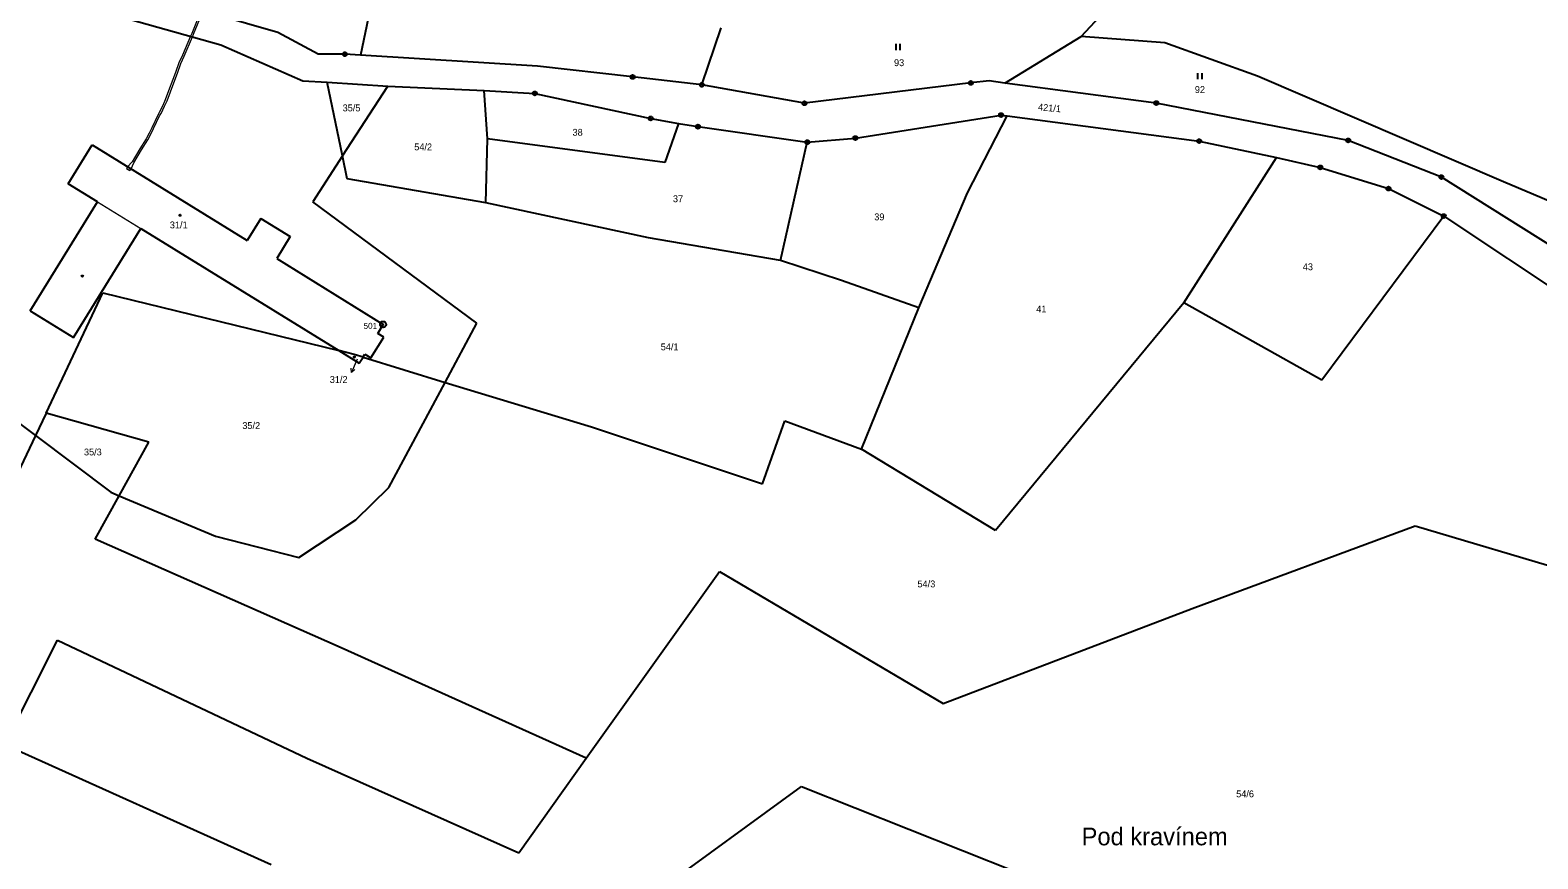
# Model space of a CAD drawing. Extents: x -791548 to -789311, y -1142631 to -1140855.
# Drawn here: x -790140.3 to -789765.7, y -1142374.6 to -1142168.7 of the extents above; entities that cross this region are included whole.
import ezdxf
from ezdxf.enums import TextEntityAlignment as Align

# ---------------------------------------------------------------- set-up
doc = ezdxf.new("R2010")
doc.units = 0
doc.header["$LTSCALE"] = 0.68
for name, color, linetype, lineweight in [('1', 7, 'Continuous', 25), ('13', 7, 'Continuous', 13), ('3', 7, 'Continuous', 25), ('4', 7, 'Continuous', 13), ('5', 7, 'Continuous', 25), ('7', 7, 'Continuous', 13), ('8', 7, 'Continuous', 25)]:
    doc.layers.add(name, color=color, linetype=linetype, lineweight=lineweight)
doc.layers.add('2', color=7, linetype='Continuous')

msp = doc.modelspace()

# ---------------------------------------------------------------- linework, layer by layer
at = {"layer": '1'}
for p, q in [((-790049.96, -1142135.49), (-790058.25, -1142174.9)), ((-790078.79, -1142169.26), (-790128.15, -1142154.89)), ((-789879.15, -1142170.27), (-789866.64, -1142156.74)), ((-790126.91, -1142162.79), (-790092.94, -1142172.32)), ((-790068.73, -1142174.67), (-790078.79, -1142169.26)), ((-789973.41, -1142182.27), (-789968.63, -1142168.11)), ((-789898.1, -1142181.88), (-789879.15, -1142170.27)), ((-789858.35, -1142171.87), (-789879.15, -1142170.27)), ((-790092.94, -1142172.32), (-790072.55, -1142181.25)), ((-789835.32, -1142180.11), (-789858.35, -1142171.87)), ((-790062.15, -1142174.65), (-790068.73, -1142174.67)), ((-790058.25, -1142174.9), (-790062.15, -1142174.65)), ((-790014.24, -1142177.64), (-790058.25, -1142174.9)), ((-789990.63, -1142180.31), (-790014.24, -1142177.64)), ((-790072.55, -1142181.25), (-790066.55, -1142181.6)), ((-790062.72, -1142199.92), (-790066.55, -1142181.6)), ((-790066.55, -1142181.6), (-790051.46, -1142182.57)), ((-789973.41, -1142182.27), (-789990.63, -1142180.31)), ((-789902.03, -1142181.26), (-789906.58, -1142181.8)), ((-789898.1, -1142181.88), (-789902.03, -1142181.26)), ((-789774.23, -1142206.36), (-789835.32, -1142180.11)), ((-790062.72, -1142199.92), (-790051.46, -1142182.57)), ((-790051.46, -1142182.57), (-790027.52, -1142183.69)), ((-790026.68, -1142195.7), (-790027.52, -1142183.69)), ((-790027.52, -1142183.69), (-790014.93, -1142184.4)), ((-790014.93, -1142184.4), (-789986.12, -1142190.62)), ((-789947.92, -1142186.86), (-789973.41, -1142182.27)), ((-789906.58, -1142181.8), (-789947.92, -1142186.86)), ((-789860.49, -1142186.79), (-789898.1, -1142181.88)), ((-789812.79, -1142196.06), (-789860.49, -1142186.79)), ((-789986.12, -1142190.62), (-789979.19, -1142191.84)), ((-789979.19, -1142191.84), (-789982.61, -1142201.56)), ((-789979.19, -1142191.84), (-789974.39, -1142192.66)), ((-789974.39, -1142192.66), (-789947.22, -1142196.51)), ((-789935.26, -1142195.48), (-789899.06, -1142189.78)), ((-789907.39, -1142209.13), (-789897.53, -1142189.94)), ((-789899.06, -1142189.78), (-789897.53, -1142189.94)), ((-789897.53, -1142189.94), (-789849.83, -1142196.25)), ((-790027.09, -1142211.59), (-790026.68, -1142195.7)), ((-789982.61, -1142201.56), (-790026.68, -1142195.7)), ((-789953.84, -1142225.89), (-789947.22, -1142196.51)), ((-789947.22, -1142196.51), (-789935.26, -1142195.48)), ((-789849.83, -1142196.25), (-789830.6, -1142200.28)), ((-789789.62, -1142205.2), (-789812.79, -1142196.06)), ((-790130.87, -1142206.84), (-790124.92, -1142197.19)), ((-790124.92, -1142197.19), (-790086.4, -1142220.91)), ((-790062.72, -1142199.92), (-790070.06, -1142211.32)), ((-790061.52, -1142205.63), (-790062.72, -1142199.92)), ((-789853.67, -1142236.46), (-789830.6, -1142200.28)), ((-789830.6, -1142200.28), (-789819.72, -1142202.78)), ((-789819.72, -1142202.78), (-789802.78, -1142208.05)), ((-790123.57, -1142211.34), (-790130.87, -1142206.84)), ((-790027.09, -1142211.59), (-790061.52, -1142205.63)), ((-789754.82, -1142227.02), (-789789.62, -1142205.2)), ((-789707.82, -1142234.54), (-789774.23, -1142206.36)), ((-790140.34, -1142238.42), (-790123.57, -1142211.34)), ((-790029.32, -1142241.51), (-790070.06, -1142211.32)), ((-789986.64, -1142220.24), (-790027.09, -1142211.59)), ((-789919.48, -1142237.67), (-789907.39, -1142209.13)), ((-789802.78, -1142208.05), (-789789.05, -1142214.87)), ((-789789.05, -1142214.87), (-789819.37, -1142255.65)), ((-789789.05, -1142214.87), (-789756.87, -1142236.32)), ((-790129.6, -1142245.01), (-790112.81, -1142217.98)), ((-790112.81, -1142217.98), (-790063.64, -1142248.3)), ((-790083.03, -1142215.47), (-790086.4, -1142220.91)), ((-790083.03, -1142215.47), (-790075.75, -1142219.92)), ((-790075.75, -1142219.92), (-790079.04, -1142225.44)), ((-789953.84, -1142225.89), (-789986.64, -1142220.24)), ((-790079.04, -1142225.44), (-790052.63, -1142241.79)), ((-789938.74, -1142230.89), (-789953.84, -1142225.89)), ((-790136.38, -1142263.82), (-790122.24, -1142233.95)), ((-790122.24, -1142233.95), (-790063.64, -1142248.3)), ((-789919.48, -1142237.67), (-789938.74, -1142230.89)), ((-789933.75, -1142272.76), (-789919.48, -1142237.67)), ((-789853.67, -1142236.46), (-789900.47, -1142293.01)), ((-789819.37, -1142255.65), (-789853.67, -1142236.46)), ((-790140.34, -1142238.42), (-790129.6, -1142245.01)), ((-790037.21, -1142256.21), (-790029.32, -1142241.51)), ((-790055.64, -1142250.09), (-790052.46, -1142244.98)), ((-790053.95, -1142244.04), (-790052.63, -1142241.79)), ((-790052.46, -1142244.98), (-790053.95, -1142244.04)), ((-790063.64, -1142248.3), (-790058.56, -1142251.43)), ((-790059.84, -1142249.23), (-790063.64, -1142248.3)), ((-790057.61, -1142249.92), (-790059.84, -1142249.23)), ((-790058.56, -1142251.43), (-790057.61, -1142249.92)), ((-790057.61, -1142249.92), (-790057.14, -1142249.16)), ((-790057.61, -1142249.92), (-790037.21, -1142256.21)), ((-790057.14, -1142249.16), (-790055.64, -1142250.09)), ((-790051.2, -1142282.28), (-790037.21, -1142256.21)), ((-790037.21, -1142256.21), (-790000.8, -1142267.23)), ((-790146.97, -1142263.43), (-790139.03, -1142269.41)), ((-790136.38, -1142263.82), (-790139.03, -1142269.41)), ((-790110.82, -1142271.03), (-790136.38, -1142263.82)), ((-790000.8, -1142267.23), (-789958.31, -1142281.43)), ((-789958.31, -1142281.43), (-789952.83, -1142265.78)), ((-789952.83, -1142265.78), (-789933.75, -1142272.76)), ((-790139.03, -1142269.41), (-790146.45, -1142285.1)), ((-790139.03, -1142269.41), (-790120.32, -1142283.49)), ((-790118.23, -1142284.37), (-790110.82, -1142271.03)), ((-789900.47, -1142293.01), (-789933.75, -1142272.76)), ((-790059.38, -1142290.32), (-790051.2, -1142282.28)), ((-790124.22, -1142295.16), (-790118.23, -1142284.37)), ((-790120.32, -1142283.49), (-790118.23, -1142284.37)), ((-790118.23, -1142284.37), (-790094.28, -1142294.4)), ((-790073.56, -1142299.68), (-790059.38, -1142290.32)), ((-789851.58, -1142312.35), (-789796.14, -1142291.81)), ((-789796.14, -1142291.81), (-789755.01, -1142304.11)), ((-790063.06, -1142322.17), (-790124.22, -1142295.16)), ((-790094.28, -1142294.4), (-790073.56, -1142299.68)), ((-790002.15, -1142349.56), (-789969.02, -1142303.16)), ((-789969.02, -1142303.16), (-789913.42, -1142335.98)), ((-789913.42, -1142335.98), (-789851.58, -1142312.35)), ((-790146.61, -1142346.2), (-790133.54, -1142320.2)), ((-790133.54, -1142320.2), (-790071.58, -1142349.56)), ((-790002.15, -1142349.56), (-790063.06, -1142322.17)), ((-790080.46, -1142376.06), (-790146.61, -1142346.2)), ((-790071.58, -1142349.56), (-790018.88, -1142373.06)), ((-790018.88, -1142373.06), (-790002.15, -1142349.56)), ((-790016.01, -1142405.65), (-789948.68, -1142356.55)), ((-789948.68, -1142356.55), (-789871.73, -1142387.1))]:
    msp.add_line(p, q, dxfattribs=at)
at = {"layer": '13'}
for points in [[(-790097.36, -1142163.86), (-790097.83, -1142163.72), (-790100.2, -1142169.49), (-790100.5, -1142170.2), (-790100.01, -1142170.34), (-790099.74, -1142169.69)], [(-790105.93, -1142183.79), (-790106.75, -1142186.01), (-790107.4, -1142187.38), (-790108.25, -1142189.17), (-790108.52, -1142189.6), (-790110.09, -1142192.93), (-790110.79, -1142194.29), (-790111.53, -1142195.68), (-790113.05, -1142198.16), (-790114.98, -1142201.4), (-790116.12, -1142202.61), (-790116.39, -1142203.03), (-790115.54, -1142203.56), (-790115.27, -1142203.13), (-790114.56, -1142201.66), (-790112.63, -1142198.42), (-790111.09, -1142195.92), (-790110.35, -1142194.53), (-790109.65, -1142193.15), (-790108.08, -1142189.84), (-790107.81, -1142189.41), (-790106.94, -1142187.6), (-790106.29, -1142186.21), (-790105.47, -1142183.97), (-790104.39, -1142181.1), (-790103.74, -1142179.35), (-790102.91, -1142177), (-790102.04, -1142175.13), (-790100.01, -1142170.34), (-790100.5, -1142170.2), (-790102.5, -1142174.93), (-790103.37, -1142176.82), (-790104.22, -1142179.17), (-790104.85, -1142180.92)]]:
    msp.add_lwpolyline(points, close=True, dxfattribs=at)
at = {"layer": '3'}
for p, q in [((-789925.161, -1142173.62), (-789925.161, -1142172.12)), ((-789924.16, -1142173.62), (-789924.16, -1142172.12)), ((-789850.121, -1142180.9), (-789850.121, -1142179.4)), ((-789849.12, -1142180.9), (-789849.12, -1142179.4))]:
    msp.add_line(p, q, dxfattribs=at)
at = {"layer": '4'}
msp.add_line((-790123.57, -1142211.34), (-790112.81, -1142217.98), dxfattribs=at)
at = {"layer": '5'}
for centre in [(-790103.0768, -1142214.6492), (-790127.3668, -1142229.7992), (-790059.7568, -1142249.9092)]:
    msp.add_circle(centre, 0.175, dxfattribs=at)
at = {"layer": '7'}
msp.add_line((-790060.464, -1142253.762), (-790059.625, -1142253.022), dxfattribs=at)
msp.add_lwpolyline([(-790059.1, -1142250.39), (-790059.34, -1142250.98), (-790060.464, -1142253.762), (-790060.553, -1142252.646)], dxfattribs=at)
at = {"layer": '8'}
for centre, radius in [((-790062.1499, -1142174.65), 0.5), ((-790062.1499, -1142174.65), 0.0303), ((-789990.6299, -1142180.31), 0.5), ((-789990.6299, -1142180.31), 0.0303), ((-789906.5799, -1142181.8), 0.5), ((-790014.9299, -1142184.4), 0.5), ((-790014.9299, -1142184.4), 0.0303), ((-789973.4099, -1142182.27), 0.5), ((-789973.4099, -1142182.27), 0.0303), ((-789906.5799, -1142181.8), 0.0303), ((-789947.9199, -1142186.86), 0.5), ((-789947.9199, -1142186.86), 0.0303), ((-789860.4899, -1142186.79), 0.5), ((-789860.4899, -1142186.79), 0.0303), ((-789986.1199, -1142190.62), 0.5), ((-789986.1199, -1142190.62), 0.0303), ((-789974.3899, -1142192.66), 0.5), ((-789974.3899, -1142192.66), 0.0303), ((-789899.0599, -1142189.78), 0.5), ((-789899.0599, -1142189.78), 0.0303), ((-789947.2199, -1142196.51), 0.5), ((-789947.2199, -1142196.51), 0.0303), ((-789935.2599, -1142195.48), 0.5), ((-789935.2599, -1142195.48), 0.0303), ((-789849.8299, -1142196.25), 0.5), ((-789849.8299, -1142196.25), 0.0303), ((-789812.7899, -1142196.06), 0.5), ((-789812.7899, -1142196.06), 0.0303), ((-789819.7199, -1142202.78), 0.5), ((-789819.7199, -1142202.78), 0.0303), ((-789802.7799, -1142208.05), 0.5), ((-789789.6199, -1142205.2), 0.5), ((-789789.6199, -1142205.2), 0.0303), ((-789802.7799, -1142208.05), 0.0303), ((-789789.0499, -1142214.87), 0.5), ((-789789.0499, -1142214.87), 0.0303), ((-790052.63, -1142241.7898), 0.75), ((-790052.63, -1142241.7898), 0.03)]:
    msp.add_circle(centre, radius, dxfattribs=at)

# ---------------------------------------------------------------- texts
at = {"layer": '2'}
for s, p in [('93', (-789924.399, -1142177.622)), ('92', (-789849.639, -1142184.295)), ('35/5', (-790060.469, -1142188.852)), ('38', (-790004.289, -1142194.912)), ('54/2', (-790042.679, -1142198.542)), ('37', (-789979.339, -1142211.422)), ('39', (-789929.309, -1142215.922)), ('31/1', (-790103.419, -1142217.922)), ('43', (-789822.809, -1142228.322)), ('41', (-789889.049, -1142238.822)), ('54/1', (-789981.419, -1142248.212)), ('35/2', (-790085.399, -1142267.772)), ('35/3', (-790124.759, -1142274.332)), ('54/3', (-789917.619, -1142307.112)), ('54/6', (-789838.419, -1142359.272))]:
    msp.add_text(s, height=1.7, dxfattribs=at).set_placement(p, align=Align.CENTER)
msp.add_text('421/1', height=1.7, rotation=355, dxfattribs=at).set_placement((-789887.0941, -1142188.8505), align=Align.CENTER)
msp.add_text('31/2', height=1.7, dxfattribs=at).set_placement((-790061.459, -1142256.325), align=Align.RIGHT)
at = {"layer": '7'}
msp.add_text('Pod kravínem', height=4.4, dxfattribs=at).set_placement((-789879.04, -1142371.2))
at = {"layer": '8'}
msp.add_text('501', height=1.5, dxfattribs=at).set_placement((-790054.129, -1142242.907), align=Align.RIGHT)

doc.saveas('drawing.dxf')
